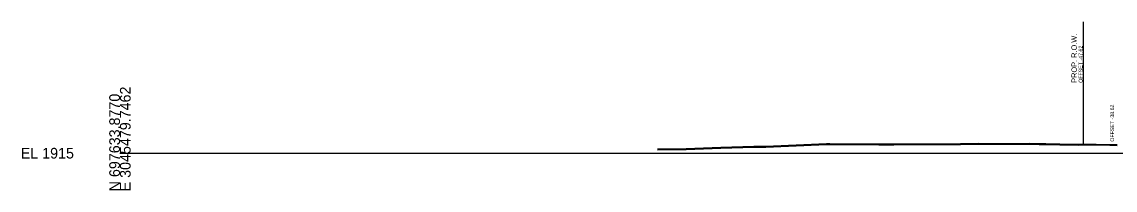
# Model space of a CAD drawing. Extents: x 1574 to 14903, y 7971 to 16537.
# Drawn here: x 4474.3 to 4760.7, y 11490.3 to 11534.5 of the extents above; entities that cross this region are included whole.
import ezdxf

# ---------------------------------------------------------------- set-up
doc = ezdxf.new("R2010")
doc.units = 0
for name, color, linetype in [('DESIGN - ROW - Right-of-Way and Easement Labels', 7, 'Continuous'), ('DESIGN - ROW - Right-of-Way Linework', 7, 'Continuous'), ('DESIGN - SHEET - Light Grid', 7, 'Continuous'), ('DESIGN - TYPICAL - Slope Tie Text', 7, 'Continuous'), ('SURVEY - GROUND - Bottom of Topsoil Layer', 7, 'Continuous'), ('SURVEY - GROUND - Top of Ground', 7, 'Continuous')]:
    doc.layers.add(name, color=color, linetype=linetype)

msp = doc.modelspace()

# ---------------------------------------------------------------- linework, layer by layer
at = {"layer": 'DESIGN - ROW - Right-of-Way Linework'}
msp.add_line((4752.38, 11502.47), (4752.38, 11534.47), dxfattribs=at)
at = {"layer": 'DESIGN - SHEET - Light Grid'}
msp.add_line((4500, 11500), (4800, 11500), dxfattribs=at)
at = {"layer": 'SURVEY - GROUND - Bottom of Topsoil Layer'}
for p, q in [((4640.76, 11500.93), (4648.3, 11500.97)), ((4648.3, 11500.97), (4657.41, 11501.32)), ((4657.41, 11501.32), (4666.06, 11501.56)), ((4666.06, 11501.56), (4669.15, 11501.62)), ((4669.15, 11501.62), (4685.09, 11502.26)), ((4685.09, 11502.26), (4685.93, 11502.26)), ((4685.93, 11502.26), (4698.79, 11502.22)), ((4698.79, 11502.22), (4702.66, 11502.18)), ((4702.66, 11502.18), (4720.13, 11502.31)), ((4720.13, 11502.31), (4724.81, 11502.38)), ((4724.81, 11502.38), (4731.69, 11502.34)), ((4731.69, 11502.34), (4738.35, 11502.37)), ((4738.35, 11502.37), (4740.73, 11502.28)), ((4740.73, 11502.28), (4742.53, 11502.26)), ((4742.53, 11502.26), (4746.15, 11502.19)), ((4746.15, 11502.19), (4751.08, 11502.15)), ((4751.08, 11502.15), (4752.19, 11502.22)), ((4752.19, 11502.22), (4759.26, 11502.07)), ((4759.26, 11502.07), (4760.48, 11502.08)), ((4760.48, 11502.08), (4761.23, 11502.03))]:
    msp.add_line(p, q, dxfattribs=at)
at = {"layer": 'SURVEY - GROUND - Top of Ground'}
msp.add_lwpolyline([(4640.76, 11501.18), (4648.3, 11501.22), (4657.41, 11501.57), (4666.06, 11501.81), (4669.15, 11501.87), (4685.09, 11502.51), (4685.93, 11502.51), (4698.79, 11502.47), (4702.66, 11502.43), (4720.13, 11502.56), (4724.81, 11502.63), (4731.69, 11502.59), (4738.35, 11502.62), (4740.73, 11502.53), (4742.53, 11502.51), (4746.15, 11502.44), (4751.08, 11502.4), (4752.19, 11502.47), (4759.26, 11502.32), (4760.48, 11502.33), (4761.23, 11502.28)], dxfattribs=at)

# ---------------------------------------------------------------- texts
at = {"layer": 'DESIGN - ROW - Right-of-Way and Easement Labels'}
for s, height, p in [('PROP. R.O.W.', 1.4, (4750.63, 11518.47)), ('OFFSET -47.62', 1, (4752.13, 11518.47))]:
    msp.add_text(s, height=height, rotation=90, dxfattribs=at).set_placement(p)
at = {"layer": 'DESIGN - SHEET - Light Grid'}
for s, p in [('N 697633.8770', (4500, 11490)), ('E 3045479.7462', (4502.8, 11490))]:
    msp.add_text(s, height=2.8, rotation=90, dxfattribs=at).set_placement(p)
msp.add_text('EL 1915', height=2.8, dxfattribs=at).set_placement((4474, 11498.6))
at = {"layer": 'DESIGN - TYPICAL - Slope Tie Text'}
msp.add_text('OFFSET -38.62', height=1, rotation=90, dxfattribs=at).set_placement((4760.39, 11503.03))

doc.saveas('drawing.dxf')
